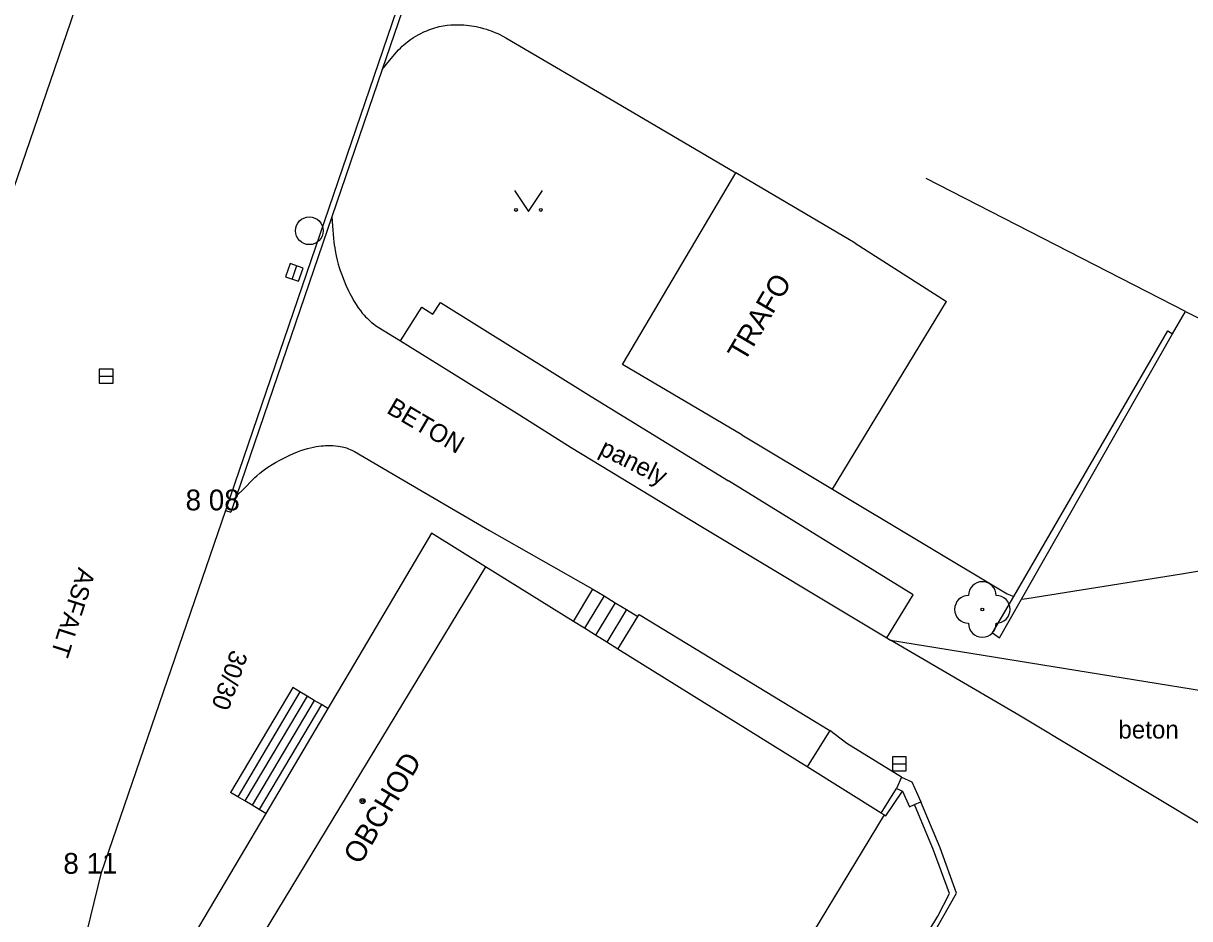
# Model space of a CAD drawing. Extents: x -538441 to -536770, y -1181008 to -1179809.
# Drawn here: x -538161.78 to -538119.74, y -1180855.09 to -1180822.81 of the extents above; entities that cross this region are included whole.
import ezdxf

# ---------------------------------------------------------------- set-up
doc = ezdxf.new("R2010")
doc.units = 0
for name, color, linetype in [('Vrstva 10', 7, 'Continuous'), ('Vrstva 11', 7, 'Continuous'), ('Vrstva 22', 7, 'Continuous'), ('Vrstva 27', 7, 'Continuous'), ('Vrstva 36', 7, 'Continuous'), ('Vrstva 39', 7, 'Continuous'), ('Vrstva 4', 7, 'Continuous'), ('Vrstva 40', 7, 'Continuous'), ('Vrstva 41', 7, 'Continuous'), ('Vrstva 5', 7, 'Continuous'), ('Vrstva 7', 7, 'Continuous')]:
    doc.layers.add(name, color=color, linetype=linetype)

msp = doc.modelspace()

# ---------------------------------------------------------------- linework, layer by layer
at = {"layer": 'Vrstva 10'}
for p, q in [((-538146.86, -1180818.05), (-538154.49, -1180840.37)), ((-538167.84, -1180845.41), (-538158.94, -1180819.46)), ((-538143.89, -1180836.92), (-538142.03, -1180838.1)), ((-538142.03, -1180838.1), (-538137.36, -1180840.94)), ((-538154.49, -1180840.37), (-538158.99, -1180853.47)), ((-538137.36, -1180840.94), (-538130.657, -1180844.968)), ((-538144.97, -1180841.1), (-538141.25, -1180843.21)), ((-538130.657, -1180844.968), (-538130.52, -1180845.05)), ((-538158.99, -1180853.47), (-538159.96, -1180857.49))]:
    msp.add_line(p, q, dxfattribs=at)
for points in [[(-538141.25, -1180843.21), (-538140.845, -1180843.455), (-538140.44, -1180843.7), (-538140.035, -1180843.945), (-538139.63, -1180844.19)], [(-538130.12, -1180849.99), (-538132.09, -1180848.78), (-538132.71, -1180848.3)]]:
    msp.add_lwpolyline(points, dxfattribs=at)
at = {"layer": 'Vrstva 11'}
for p, q in [((-538140.245, -1180825.765), (-538136.1, -1180828.2)), ((-538146.74, -1180832.87), (-538141.31, -1180836.26)), ((-538146.44, -1180835.34), (-538143.89, -1180836.92)), ((-538141.31, -1180836.26), (-538136.36, -1180839.31)), ((-538129.699, -1180843.414), (-538136.36, -1180839.31)), ((-538147.405, -1180839.675), (-538144.97, -1180841.1)), ((-538154.49, -1180840.37), (-538154.3, -1180840.434)), ((-538141.953, -1180844.371), (-538141.25, -1180843.21)), ((-538140.845, -1180843.455), (-538141.551, -1180844.622)), ((-538130.657, -1180844.968), (-538129.699, -1180843.414)), ((-538140.44, -1180843.7), (-538141.149, -1180844.872)), ((-538140.035, -1180843.945), (-538140.747, -1180845.122)), ((-538139.58, -1180844.12), (-538132.71, -1180848.3)), ((-538125.89, -1180847.75), (-538130.52, -1180845.05)), ((-538130.52, -1180845.05), (-538115.06, -1180847.56)), ((-538152.07, -1180846.76), (-538154.31, -1180850.54)), ((-538151.811, -1180846.912), (-538154.051, -1180850.692)), ((-538151.553, -1180847.065), (-538153.793, -1180850.845)), ((-538151.295, -1180847.218), (-538153.535, -1180850.998)), ((-538151.037, -1180847.371), (-538153.277, -1180851.151)), ((-538118.94, -1180851.94), (-538125.89, -1180847.75)), ((-538132.71, -1180848.3), (-538133.53, -1180849.617))]:
    msp.add_line(p, q, dxfattribs=at)
for points in [[(-538146.67, -1180818.114), (-538148.85, -1180824.47)], [(-538148.85, -1180824.47), (-538148.581, -1180824.152), (-538148.323, -1180823.848), (-538148.255, -1180823.771), (-538148.188, -1180823.701), (-538148.122, -1180823.638), (-538148.058, -1180823.581), (-538147.996, -1180823.529), (-538147.937, -1180823.481), (-538147.822, -1180823.397), (-538147.718, -1180823.327), (-538147.625, -1180823.27), (-538147.542, -1180823.223), (-538147.469, -1180823.184), (-538147.338, -1180823.12), (-538147.239, -1180823.077), (-538147.165, -1180823.047), (-538147.052, -1180823.006), (-538146.94, -1180822.97), (-538146.864, -1180822.949), (-538146.79, -1180822.931), (-538146.717, -1180822.915), (-538146.645, -1180822.902), (-538146.505, -1180822.881), (-538146.371, -1180822.869), (-538146.244, -1180822.862), (-538146.124, -1180822.86), (-538146.011, -1180822.863), (-538145.904, -1180822.869), (-538145.804, -1180822.878), (-538145.711, -1180822.888), (-538145.623, -1180822.901), (-538145.459, -1180822.929), (-538145.317, -1180822.961), (-538145.194, -1180822.993), (-538145.087, -1180823.024), (-538144.995, -1180823.054), (-538144.915, -1180823.083), (-538144.778, -1180823.137), (-538144.678, -1180823.181), (-538144.604, -1180823.216), (-538144.495, -1180823.271), (-538144.39, -1180823.33), (-538140.245, -1180825.765)], [(-538148.85, -1180824.47), (-538150.659, -1180829.784)], [(-538150.659, -1180829.784), (-538154.101, -1180839.851)], [(-538150.659, -1180829.784), (-538150.634, -1180830.108), (-538150.597, -1180830.565), (-538150.586, -1180830.687), (-538150.572, -1180830.8), (-538150.556, -1180830.906), (-538150.54, -1180831.005), (-538150.503, -1180831.189), (-538150.465, -1180831.349), (-538150.427, -1180831.489), (-538150.391, -1180831.61), (-538150.357, -1180831.716), (-538150.292, -1180831.901), (-538150.239, -1180832.039), (-538150.153, -1180832.245), (-538150.06, -1180832.45), (-538150.012, -1180832.549), (-538149.965, -1180832.64), (-538149.919, -1180832.724), (-538149.875, -1180832.802), (-538149.787, -1180832.945), (-538149.705, -1180833.066), (-538149.629, -1180833.168), (-538149.56, -1180833.255), (-538149.497, -1180833.328), (-538149.441, -1180833.39), (-538149.389, -1180833.442), (-538149.296, -1180833.53), (-538149.223, -1180833.592), (-538149.167, -1180833.637), (-538149.08, -1180833.701), (-538148.99, -1180833.76), (-538148.178, -1180834.263), (-538146.44, -1180835.34)], [(-538148.178, -1180834.263), (-538147.42, -1180833.04), (-538147.02, -1180833.3), (-538146.74, -1180832.87)], [(-538154.101, -1180839.851), (-538153.836, -1180839.588), (-538153.493, -1180839.246), (-538153.429, -1180839.185), (-538153.368, -1180839.129), (-538153.25, -1180839.029), (-538153.142, -1180838.946), (-538153.046, -1180838.876), (-538152.96, -1180838.818), (-538152.805, -1180838.719), (-538152.686, -1180838.649), (-538152.505, -1180838.547), (-538152.32, -1180838.45), (-538152.176, -1180838.379), (-538152.036, -1180838.317), (-538151.902, -1180838.263), (-538151.773, -1180838.216), (-538151.65, -1180838.176), (-538151.533, -1180838.142), (-538151.423, -1180838.113), (-538151.32, -1180838.09), (-538151.222, -1180838.071), (-538151.13, -1180838.056), (-538151.045, -1180838.045), (-538150.964, -1180838.037), (-538150.889, -1180838.032), (-538150.749, -1180838.027), (-538150.628, -1180838.03), (-538150.523, -1180838.038), (-538150.432, -1180838.049), (-538150.354, -1180838.062), (-538150.286, -1180838.076), (-538150.227, -1180838.091), (-538150.127, -1180838.121), (-538150.053, -1180838.147), (-538149.998, -1180838.17), (-538149.918, -1180838.207), (-538149.84, -1180838.25), (-538147.405, -1180839.675)], [(-538154.101, -1180839.851), (-538154.3, -1180840.434)], [(-538140.345, -1180845.373), (-538139.63, -1180844.19), (-538139.58, -1180844.12)], [(-538150.801, -1180847.512), (-538151.037, -1180847.371), (-538151.295, -1180847.218), (-538151.553, -1180847.065), (-538151.811, -1180846.912), (-538152.07, -1180846.76)], [(-538153.038, -1180851.294), (-538153.277, -1180851.151), (-538153.535, -1180850.998), (-538153.793, -1180850.845), (-538154.051, -1180850.692), (-538154.31, -1180850.54)]]:
    msp.add_lwpolyline(points, dxfattribs=at)
at = {"layer": 'Vrstva 22'}
msp.add_circle((-538127.21, -1180843.94), 0.05, dxfattribs=at)
for centre, start, end in [((-538127.21, -1180843.44), 0, 180), ((-538127.71, -1180843.94), 90, 270), ((-538126.71, -1180843.94), 270, 90), ((-538127.21, -1180844.44), 180, 0)]:
    msp.add_arc(centre, 0.5, start, end, dxfattribs=at)
at = {"layer": 'Vrstva 27'}
for p, q in [((-538151.929, -1180831.554), (-538152.091, -1180832.026)), ((-538159.04, -1180835.53), (-538158.54, -1180835.53)), ((-538130.45, -1180849.51), (-538129.95, -1180849.51))]:
    msp.add_line(p, q, dxfattribs=at)
for points in [[(-538152.165, -1180831.472), (-538152.328, -1180831.945), (-538151.855, -1180832.108), (-538151.692, -1180831.635)], [(-538159.04, -1180835.78), (-538158.54, -1180835.78), (-538158.54, -1180835.28), (-538159.04, -1180835.28)], [(-538130.45, -1180849.76), (-538129.95, -1180849.76), (-538129.95, -1180849.26), (-538130.45, -1180849.26)]]:
    msp.add_lwpolyline(points, close=True, dxfattribs=at)
msp.add_circle((-538151.47, -1180830.29), 0.5, dxfattribs=at)
at = {"layer": 'Vrstva 36'}
msp.add_lwpolyline([(-538144.07, -1180828.84), (-538143.57, -1180829.59), (-538143.07, -1180828.84)], dxfattribs=at)
for centre in [(-538144.02, -1180829.54), (-538143.121, -1180829.54)]:
    msp.add_circle(centre, 0.05, dxfattribs=at)
at = {"layer": 'Vrstva 39'}
for radius in [0.09, 0.0398]:
    msp.add_circle((-538149.55, -1180850.85), radius, dxfattribs=at)
at = {"layer": 'Vrstva 5'}
for p, q in [((-538140.18, -1180835.11), (-538136.1, -1180828.2)), ((-538131.794, -1180830.742), (-538136.1, -1180828.2)), ((-538131.794, -1180830.742), (-538128.499, -1180832.837)), ((-538132.61, -1180839.6), (-538128.499, -1180832.837)), ((-538135.874, -1180837.652), (-538140.18, -1180835.11)), ((-538135.874, -1180837.652), (-538132.61, -1180839.6)), ((-538145.118, -1180842.4), (-538154.831, -1180858.427))]:
    msp.add_line(p, q, dxfattribs=at)
for points in [[(-538147.06, -1180841.19), (-538150, -1180846.159)], [(-538145.118, -1180842.4), (-538147.06, -1180841.19)], [(-538141.953, -1180844.371), (-538145.118, -1180842.4)], [(-538141.551, -1180844.622), (-538141.953, -1180844.371)], [(-538141.149, -1180844.872), (-538141.551, -1180844.622)], [(-538140.747, -1180845.122), (-538141.149, -1180844.872)], [(-538140.345, -1180845.373), (-538140.747, -1180845.122)], [(-538133.53, -1180849.617), (-538140.345, -1180845.373)], [(-538150, -1180846.159), (-538150.718, -1180847.372)], [(-538150.801, -1180847.512), (-538153.038, -1180851.294)], [(-538150.718, -1180847.372), (-538150.801, -1180847.512)], [(-538130.854, -1180851.284), (-538133.53, -1180849.617)], [(-538153.038, -1180851.294), (-538156.74, -1180857.55)], [(-538130.748, -1180851.35), (-538134.605, -1180857.711)], [(-538130.748, -1180851.35), (-538130.854, -1180851.284)]]:
    msp.add_lwpolyline(points, dxfattribs=at)
at = {"layer": 'Vrstva 7'}
for p, q in [((-538119.888, -1180833.2), (-538129.239, -1180828.401)), ((-538120.35, -1180834), (-538119.888, -1180833.2)), ((-538119.888, -1180833.2), (-538105.94, -1180840.3)), ((-538132.61, -1180839.6), (-538126.32, -1180843.38)), ((-538120.03, -1180842.66), (-538114.25, -1180841.71)), ((-538125.6, -1180843.55), (-538120.03, -1180842.66)), ((-538126.32, -1180843.38), (-538126.08, -1180843.48)), ((-538125.8, -1180843.57), (-538125.6, -1180843.55)), ((-538126.839, -1180844.789), (-538126.591, -1180844.959)), ((-538130.854, -1180851.284), (-538130.308, -1180850.399)), ((-538128.965, -1180852.615), (-538129.66, -1180850.978)), ((-538128.39, -1180854.18), (-538128.965, -1180852.615)), ((-538131.8, -1180860.62), (-538128.14, -1180854.17)), ((-538128.82, -1180855), (-538128.39, -1180854.18)), ((-538135.754, -1180866.405), (-538128.82, -1180855))]:
    msp.add_line(p, q, dxfattribs=at)
for points in [[(-538126.08, -1180843.48), (-538120.521, -1180833.897)], [(-538125.8, -1180843.57), (-538120.35, -1180834)], [(-538120.521, -1180833.897), (-538120.35, -1180834)], [(-538126.839, -1180844.789), (-538126.08, -1180843.48)], [(-538126.591, -1180844.959), (-538125.8, -1180843.57)], [(-538130.12, -1180849.99), (-538130.308, -1180850.399), (-538130.092, -1180850.498), (-538129.841, -1180851.063), (-538129.66, -1180850.978), (-538129.43, -1180850.88)], [(-538130.12, -1180849.99), (-538129.75, -1180850.16), (-538129.43, -1180850.88)], [(-538130.748, -1180851.35), (-538130.691, -1180851.383), (-538130.092, -1180850.498)], [(-538128.14, -1180854.17), (-538128.73, -1180852.53), (-538129.43, -1180850.88)]]:
    msp.add_lwpolyline(points, dxfattribs=at)

# ---------------------------------------------------------------- texts
at = {"layer": 'Vrstva 4'}
for s, p in [(' 8 08', (-538156.209, -1180840.37)), (' 8 11', (-538160.615, -1180853.47))]:
    msp.add_text(s, height=0.75, dxfattribs=at).set_placement(p)
at = {"layer": 'Vrstva 40'}
for s, rotation, p in [('BETON', 329.6632, (-538148.721, -1180836.837)), ('panely', 333.1823, (-538141.066, -1180838.328)), ('ASFALT', 252.1511, (-538159.787, -1180842.397)), ('30/30', 250.7542, (-538154.288, -1180845.362))]:
    msp.add_text(s, height=0.65, rotation=rotation, dxfattribs=at).set_placement(p)
msp.add_text('beton', height=0.65, dxfattribs=at).set_placement((-538122.305, -1180848.595))
at = {"layer": 'Vrstva 41'}
for s, rotation, p in [('TRAFO', 59.4403, (-538135.789, -1180835.055)), ('OBCHOD', 59.3877, (-538149.64, -1180853.176))]:
    msp.add_text(s, height=0.75, rotation=rotation, dxfattribs=at).set_placement(p)

doc.saveas('drawing.dxf')
